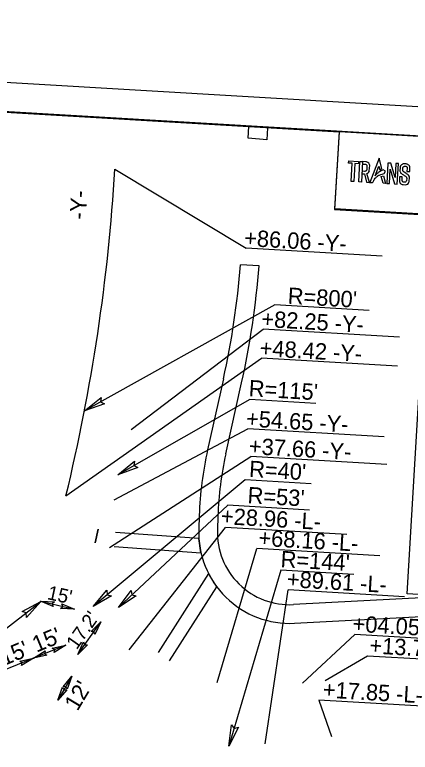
# Model space of a CAD drawing. Extents: x 2011491 to 2012372, y 444688 to 445287.
# Drawn here: x 2012019.7 to 2012189.4, y 444971.3 to 445287.5 of the extents above; entities that cross this region are included whole.
import ezdxf

# ---------------------------------------------------------------- set-up
doc = ezdxf.new("R2010")
doc.units = 0
for name, color, linetype in [('Old_Level_1', 7, 'Continuous'), ('Old_Level_58', 7, 'Continuous'), ('Prop Dimension', 7, 'Continuous'), ('Prop Dimension Text', 7, 'Continuous'), ('Prop Lane Lines', 7, 'Continuous'), ('Prop Shade Medium', 7, 'Continuous'), ('Prop Terminator CELL', 7, 'Continuous'), ('Sheet Clip Boundary CELL', 7, 'Continuous'), ('Sheet Plan And Profile CELL', 7, 'Continuous'), ('Sheet Plot Border Outside CELL', 7, 'Continuous')]:
    doc.layers.add(name, color=color, linetype=linetype)

msp = doc.modelspace()

# ---------------------------------------------------------------- linework, layer by layer
at = {"layer": 'Old_Level_1'}
msp.add_line((2012106.84, 445072.53), (2012106.63, 445066.62), dxfattribs=at)
for points in [[(2012162.97, 445224.83), (2012167.2, 445224.58), (2012167.14, 445223.55), (2012165.59, 445223.64), (2012165.14, 445215.94), (2012163.97, 445216.01), (2012164.42, 445223.76), (2012162.93, 445223.84)], [(2012167.78, 445224.54), (2012168.93, 445224.48), (2012168.42, 445215.71), (2012167.27, 445215.78)], [(2012176.05, 445225.99), (2012172.09, 445215.53), (2012173.2, 445215.47), (2012173.4, 445215.88), (2012173.72, 445216.44), (2012173.89, 445216.75), (2012174.09, 445217.01), (2012174.38, 445217.37), (2012174.55, 445217.59), (2012174.76, 445217.78), (2012174.96, 445217.96), (2012175.21, 445218.2), (2012175.43, 445218.32), (2012175.64, 445218.47), (2012175.93, 445218.62), (2012176.19, 445218.74), (2012176.81, 445218.99), (2012177.32, 445219.17), (2012178.16, 445219.4), (2012178.79, 445220.43), (2012177.73, 445220.97), (2012176.89, 445220.58), (2012176.18, 445220.17), (2012175.66, 445219.8), (2012175.39, 445219.6), (2012175.11, 445219.34), (2012174.82, 445219.07), (2012174.61, 445218.87), (2012174.4, 445218.56), (2012174.29, 445218.38), (2012175.85, 445222.49), (2012176.26, 445221.01), (2012177.24, 445221.59)], [(2012168.87, 445223.44), (2012170.06, 445223.37), (2012170.21, 445223.33), (2012170.41, 445223.24), (2012170.56, 445223.12), (2012170.67, 445222.98), (2012170.74, 445222.81), (2012170.79, 445222.68), (2012170.78, 445222.39), (2012170.71, 445221.14), (2012170.67, 445220.98), (2012170.61, 445220.76), (2012170.54, 445220.62), (2012170.43, 445220.5), (2012170.29, 445220.4), (2012170.07, 445220.33), (2012169.91, 445220.32), (2012169.74, 445220.31), (2012168.69, 445220.37), (2012168.64, 445219.31), (2012169.69, 445219.26), (2012170.66, 445215.61), (2012171.87, 445215.56), (2012170.77, 445219.4), (2012170.96, 445219.45), (2012171.24, 445219.64), (2012171.5, 445219.89), (2012171.69, 445220.19), (2012171.82, 445220.5), (2012171.81, 445220.6), (2012171.97, 445222.87), (2012171.89, 445223.25), (2012171.73, 445223.6), (2012171.54, 445223.85), (2012171.2, 445224.11), (2012170.87, 445224.24), (2012170.54, 445224.37), (2012170.34, 445224.38), (2012168.93, 445224.48)], [(2012179.81, 445223.85), (2012179.31, 445215.14), (2012180.42, 445215.07), (2012180.78, 445221.2), (2012182.64, 445214.93), (2012183.76, 445214.88), (2012184.27, 445223.62), (2012183.18, 445223.68), (2012182.83, 445217.7), (2012180.99, 445223.79)], [(2012187.96, 445220.28), (2012189.12, 445220.21), (2012189.22, 445221.95), (2012189.14, 445222.31), (2012189.02, 445222.61), (2012188.88, 445222.81), (2012188.71, 445223), (2012188.5, 445223.15), (2012188.29, 445223.25), (2012188.29, 445223.25), (2012188.07, 445223.36), (2012187.83, 445223.44), (2012187.67, 445223.49), (2012186.8, 445223.52), (2012186.53, 445223.49), (2012186.3, 445223.47), (2012186.06, 445223.36), (2012185.85, 445223.27), (2012185.65, 445223.14), (2012185.48, 445222.99), (2012185.35, 445222.81), (2012185.24, 445222.62), (2012185.1, 445222.28), (2012185.06, 445222.03), (2012184.96, 445220.44), (2012185.01, 445220.2), (2012185.11, 445219.95), (2012185.24, 445219.74), (2012185.38, 445219.57), (2012185.59, 445219.39), (2012185.81, 445219.2), (2012185.94, 445219.08), (2012186.18, 445218.96), (2012186.41, 445218.83), (2012186.6, 445218.69), (2012186.81, 445218.53), (2012187.07, 445218.39), (2012187.28, 445218.26), (2012187.48, 445218.09), (2012187.63, 445217.94), (2012187.75, 445217.81), (2012187.81, 445217.57), (2012187.85, 445217.42), (2012187.76, 445216.3), (2012187.67, 445216.06), (2012187.53, 445215.86), (2012187.36, 445215.73), (2012187.18, 445215.66), (2012187.01, 445215.63), (2012186.53, 445215.65), (2012186.37, 445215.7), (2012186.21, 445215.81), (2012186.05, 445215.91), (2012185.99, 445216.09), (2012185.93, 445216.26), (2012185.88, 445216.39), (2012185.95, 445217.95), (2012184.79, 445218), (2012184.7, 445216.15), (2012184.75, 445216.01), (2012184.86, 445215.57), (2012184.94, 445215.42), (2012185.05, 445215.25), (2012185.23, 445215.05), (2012185.38, 445214.95), (2012185.59, 445214.84), (2012185.67, 445214.81), (2012185.88, 445214.7), (2012186.14, 445214.66), (2012186.34, 445214.63), (2012187.41, 445214.59), (2012187.71, 445214.65), (2012188.13, 445214.81), (2012188.27, 445214.86), (2012188.61, 445215.24), (2012188.8, 445215.62), (2012188.9, 445215.97), (2012188.97, 445217.68), (2012188.98, 445217.92), (2012188.93, 445218.11), (2012188.84, 445218.29), (2012188.59, 445218.69), (2012188.26, 445218.99), (2012187.79, 445219.3), (2012187.43, 445219.55), (2012186.72, 445219.97), (2012186.36, 445220.27), (2012186.21, 445220.5), (2012186.18, 445220.64), (2012186.15, 445220.78), (2012186.24, 445222), (2012186.31, 445222.12), (2012186.38, 445222.24), (2012186.48, 445222.31), (2012186.6, 445222.4), (2012186.73, 445222.45), (2012186.86, 445222.5), (2012186.93, 445222.48), (2012186.94, 445222.51), (2012187.42, 445222.48), (2012187.56, 445222.41), (2012187.69, 445222.35), (2012187.83, 445222.29), (2012187.89, 445222.19), (2012187.97, 445222.04), (2012188.01, 445221.9), (2012188.05, 445221.76), (2012188.03, 445221.61)], [(2012176.89, 445218.07), (2012177.87, 445218.4), (2012178.81, 445215.12), (2012177.76, 445215.22)], [(2012193.42, 445130.88), (2012339.99, 445122.24), (2012334.58, 445030.55), (2012188.02, 445039.19)]]:
    msp.add_lwpolyline(points, close=True, dxfattribs=at)
at = {"layer": 'Old_Level_58'}
msp.add_lwpolyline([(2012159.02, 445237.47), (2012258.87, 445231.58), (2012256.91, 445198.29), (2012157.05, 445204.18)], close=True, dxfattribs=at)
at = {"layer": 'Prop Dimension'}
for p, q in [((2012062.68, 445221.3), (2012118.91, 445187.35)), ((2012177.3, 445183.91), (2012118.91, 445187.35)), ((2012131.3, 445163.04), (2012049.6, 445117.62)), ((2012171.69, 445160.66), (2012131.3, 445163.04)), ((2012184.68, 445149.21), (2012126.3, 445152.65)), ((2012183.95, 445136.72), (2012125.56, 445140.17)), ((2012120.55, 445122.51), (2012063.97, 445090.24)), ((2012148.89, 445120.84), (2012120.55, 445122.51)), ((2012178.11, 445106.46), (2012119.73, 445109.9)), ((2012179.33, 445094.68), (2012120.94, 445098.12)), ((2012118.51, 445088.04), (2012053.28, 445033.73)), ((2012146.86, 445086.37), (2012118.51, 445088.04)), ((2012111.14, 445077.19), (2012064.19, 445033.3)), ((2012146.2, 445075.12), (2012111.14, 445077.19)), ((2012162.18, 445064.62), (2012110.18, 445067.69)), ((2012176.35, 445055.51), (2012123.55, 445058.63)), ((2012133.9, 445049.36), (2012111.59, 444973.89)), ((2012165.19, 445047.51), (2012133.9, 445049.36)), ((2012127.15, 444974.82), (2012136.93, 445040.86)), ((2012186.86, 445037.92), (2012136.93, 445040.86)), ((2011903.98, 444938.48), (2012030.95, 445035.85)), ((2012030.76, 445036.09), (2012045.34, 445032.56)), ((2012046.72, 445013.13), (2012056.67, 445027.19)), ((2012218.4, 445018.58), (2012165.6, 445021.69)), ((2012041.61, 445017.21), (2012027.71, 445011.57)), ((2012027.71, 445011.57), (2012013.8, 445005.94)), ((2012170.99, 445012.51), (2012152.91, 445001.92)), ((2012223.95, 445009.38), (2012170.99, 445012.51)), ((2012044.24, 445003.9), (2012038.18, 444993.54)), ((2012203.99, 444990.45), (2012150.17, 444993.62)), ((2012150.17, 444993.62), (2012155.64, 444978.08))]:
    msp.add_line(p, q, dxfattribs=at)
at = {"layer": 'Prop Dimension Text'}
for p, q in [((2012069.62, 445109.68), (2012126.3, 445152.65)), ((2012041.66, 445081.14), (2012125.56, 445140.17)), ((2012062.37, 445079.41), (2012119.73, 445109.9)), ((2012060.34, 445059.02), (2012120.94, 445098.12)), ((2012068.78, 445015.1), (2012110.18, 445067.69)), ((2012106.5, 445001.17), (2012123.55, 445058.63)), ((2012143.16, 445000.81), (2012165.6, 445021.69))]:
    msp.add_line(p, q, dxfattribs=at)
at = {"layer": 'Prop Lane Lines'}
msp.add_arc((2011264.13, 445269.39), 800, 346.38954, 356.55328, dxfattribs=at)
at = {"layer": 'Prop Shade Medium'}
for p, q in [((2012119.83, 445234.55), (2012120.13, 445239.48)), ((2012128.11, 445239.01), (2012127.81, 445233.89)), ((2012127.81, 445233.89), (2012119.83, 445234.55)), ((2012124.51, 445179.83), (2012116.51, 445180.22)), ((2012109.23, 445131.33), (2012102.44, 445100.9)), ((2012110.25, 445099.16), (2012117.03, 445129.59)), ((2012098.84, 445072.81), (2012098.63, 445066.91)), ((2012055.43, 445066.87), (2012054.21, 445060.99)), ((2012055.43, 445066.87), (2012054.21, 445060.99)), ((2012054.21, 445060.99), (2012055.43, 445066.87)), ((2012098.7, 445062.86), (2012062.99, 445065.44)), ((2012099.6, 445056.78), (2012098.7, 445062.86)), ((2012062.39, 445059.47), (2012099.6, 445056.78)), ((2012102.84, 445047.87), (2012081.17, 445013.98)), ((2012106.34, 445042.22), (2012102.84, 445047.87)), ((2012086.07, 445010.5), (2012106.34, 445042.22)), ((2012205.79, 445038.14), (2012139.27, 445034.57)), ((2012139.7, 445026.59), (2012262.08, 445033.14))]:
    msp.add_line(p, q, dxfattribs=at)
for centre, radius, start, end in [((2011771.52, 445206.65), 346, 347.4271, 355.6193), ((2011771.52, 445206.65), 354, 347.4271, 355.6549), ((2012252.75, 445067.38), 154, 167.4271, 177.9766), ((2012252.75, 445067.38), 146, 167.4271, 177.9766), ((2012137.61, 445065.53), 39, 177.9766, 273.0671), ((2012137.61, 445065.53), 31, 177.9766, 273.0671)]:
    msp.add_arc(centre, radius, start, end, dxfattribs=at)
at = {"layer": 'Prop Terminator CELL'}
for points in [[(2012058.22, 445120.64), (2012049.6, 445117.62), (2012056.73, 445123.42), (2012056.5, 445121.46)], [(2012072.56, 445093.36), (2012063.97, 445090.24), (2012071.04, 445096.12), (2012070.84, 445094.16)], [(2012061.18, 445038.3), (2012053.28, 445033.73), (2012059.21, 445040.75), (2012059.35, 445038.78)], [(2012071.82, 445038.32), (2012064.19, 445033.3), (2012069.71, 445040.65), (2012069.96, 445038.7)], [(2012022.86, 445031.6), (2012030.95, 445035.85), (2012024.74, 445029.07), (2012024.68, 445031.04)], [(2012036.2, 445033.74), (2012030.76, 445036.09), (2012036.72, 445035.72), (2012035.75, 445034.88)], [(2012039.89, 445034.92), (2012045.34, 445032.56), (2012039.37, 445032.94), (2012040.34, 445033.77)], [(2012052.47, 445022.99), (2012056.67, 445027.19), (2012054.12, 445021.78), (2012053.7, 445023)], [(2012035.81, 445015.94), (2012041.61, 445017.21), (2012036.55, 445014.03), (2012036.85, 445015.28)], [(2012050.92, 445017.32), (2012046.72, 445013.13), (2012049.27, 445018.53), (2012049.68, 445017.32)], [(2012033.51, 445012.84), (2012027.71, 445011.57), (2012032.77, 445014.75), (2012032.47, 445013.5)], [(2012021.91, 445010.31), (2012027.71, 445011.57), (2012022.65, 445008.4), (2012022.95, 445009.65)], [(2012040.41, 444999.36), (2012044.24, 445003.9), (2012042.16, 444998.3), (2012041.64, 444999.47)], [(2012042.01, 444998.08), (2012038.18, 444993.54), (2012040.26, 444999.14), (2012040.78, 444997.97)], [(2012115.63, 444982.08), (2012111.59, 444973.89), (2012112.62, 444983.02), (2012113.83, 444981.47)]]:
    msp.add_lwpolyline(points, close=True, dxfattribs=at)
at = {"layer": 'Sheet Clip Boundary CELL'}
for points in [[(2012353.36, 445134.84), (2012253.51, 445140.73), (2012256.91, 445198.29), (2012157.05, 445204.18), (2012159.02, 445237.47), (2011610.02, 445269.83), (2011579.13, 444745.74), (2012327.83, 444701.6)], [(2011579.79, 444746.22), (2011610.64, 445269.52), (2012158.83, 445237.2), (2012156.87, 445204), (2012256.73, 445198.11), (2012253.34, 445140.51), (2012353.28, 445134.62), (2012327.76, 444701.71)]]:
    msp.add_lwpolyline(points, close=True, dxfattribs=at)
at = {"layer": 'Sheet Plan And Profile CELL'}
msp.add_lwpolyline([(2012358.72, 445225.69), (2011610.02, 445269.83), (2011579.13, 444745.74), (2012327.83, 444701.6)], close=True, dxfattribs=at)
at = {"layer": 'Sheet Plot Border Outside CELL'}
msp.add_lwpolyline([(2011491.04, 444738.41), (2012339.57, 444688.39), (2012371.93, 445237.44), (2011523.41, 445287.46)], close=True, dxfattribs=at)

# ---------------------------------------------------------------- texts
at = {"layer": 'Prop Dimension'}
msp.add_text('-Y- ', height=7, rotation=86.5533, dxfattribs=at).set_placement((2012050.13, 445199.46))
at = {"layer": 'Prop Dimension Text'}
for s, height, rotation, p in [('+86.06 -Y-', 7, 356.6264, (2012117.96, 445188.37)), ("R=800'", 7, 356.6264, (2012136.67, 445163.58)), ('+82.25 -Y-', 7, 356.6264, (2012125.34, 445153.67)), ('+48.42 -Y-', 7, 356.6264, (2012124.61, 445141.18)), ("R=115'", 7, 356.6264, (2012119.94, 445123.9)), ('+54.65 -Y-', 7, 356.6264, (2012118.77, 445110.92)), ('+37.66 -Y-', 7, 356.6264, (2012119.98, 445099.14)), ("R=40'", 7, 356.6264, (2012120.09, 445089.3)), ("R=53'", 7, 356.6264, (2012119.43, 445078.06)), ('+28.96 -L-', 7, 356.6264, (2012108, 445069.13)), ('+68.16 -L-', 7, 356.6264, (2012124.08, 445059.82)), ("R=144'", 7, 356.6264, (2012133.61, 445050.66)), ('+89.61 -L-', 7, 356.6264, (2012136.27, 445042.12)), ("15'", 6, 347.8334, (2012033.35, 445036.93)), ("17.2'", 6, 54.6891, (2012046.27, 445014.95)), ('+04.05 -L-', 7, 356.6264, (2012164.46, 445022.98)), ("15'", 7, 22.5868, (2012029.03, 445013.92)), ("15'", 7, 22.5868, (2012015.05, 445008.19)), ('+13.72 -L-', 7, 356.6264, (2012171.68, 445013.69)), ("12'", 7, 59.1699, (2012046.62, 444988.59)), ('+17.85 -L-', 7, 356.6264, (2012151.72, 444994.75))]:
    msp.add_text(s, height=height, rotation=rotation, dxfattribs=at).set_placement(p)

doc.saveas('drawing.dxf')
